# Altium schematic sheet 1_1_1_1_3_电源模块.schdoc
size 297 x 210 mm; Device: Sheet-Symbol; Symbol: Sheet-Symbol; Name: Sheet-Symbol; @Page No: 1; @Page Count: 2; @Schematic Name: 1_1_1_1_3_电源模块; @Project Name: Altium_Altium_Altium_新硬件设计比赛pcb1234567_2025-09-07_2025-09-08_2025-09-08; @Board Name: 1_1_1_1_3_电源模块; @Update Date: 2026-05-23; @Create Time: 14:33:01; @Update Time: 16:19:45; @Page Name: 1_1_1_1_3_电源模块; @Create Date: 2026-05-21
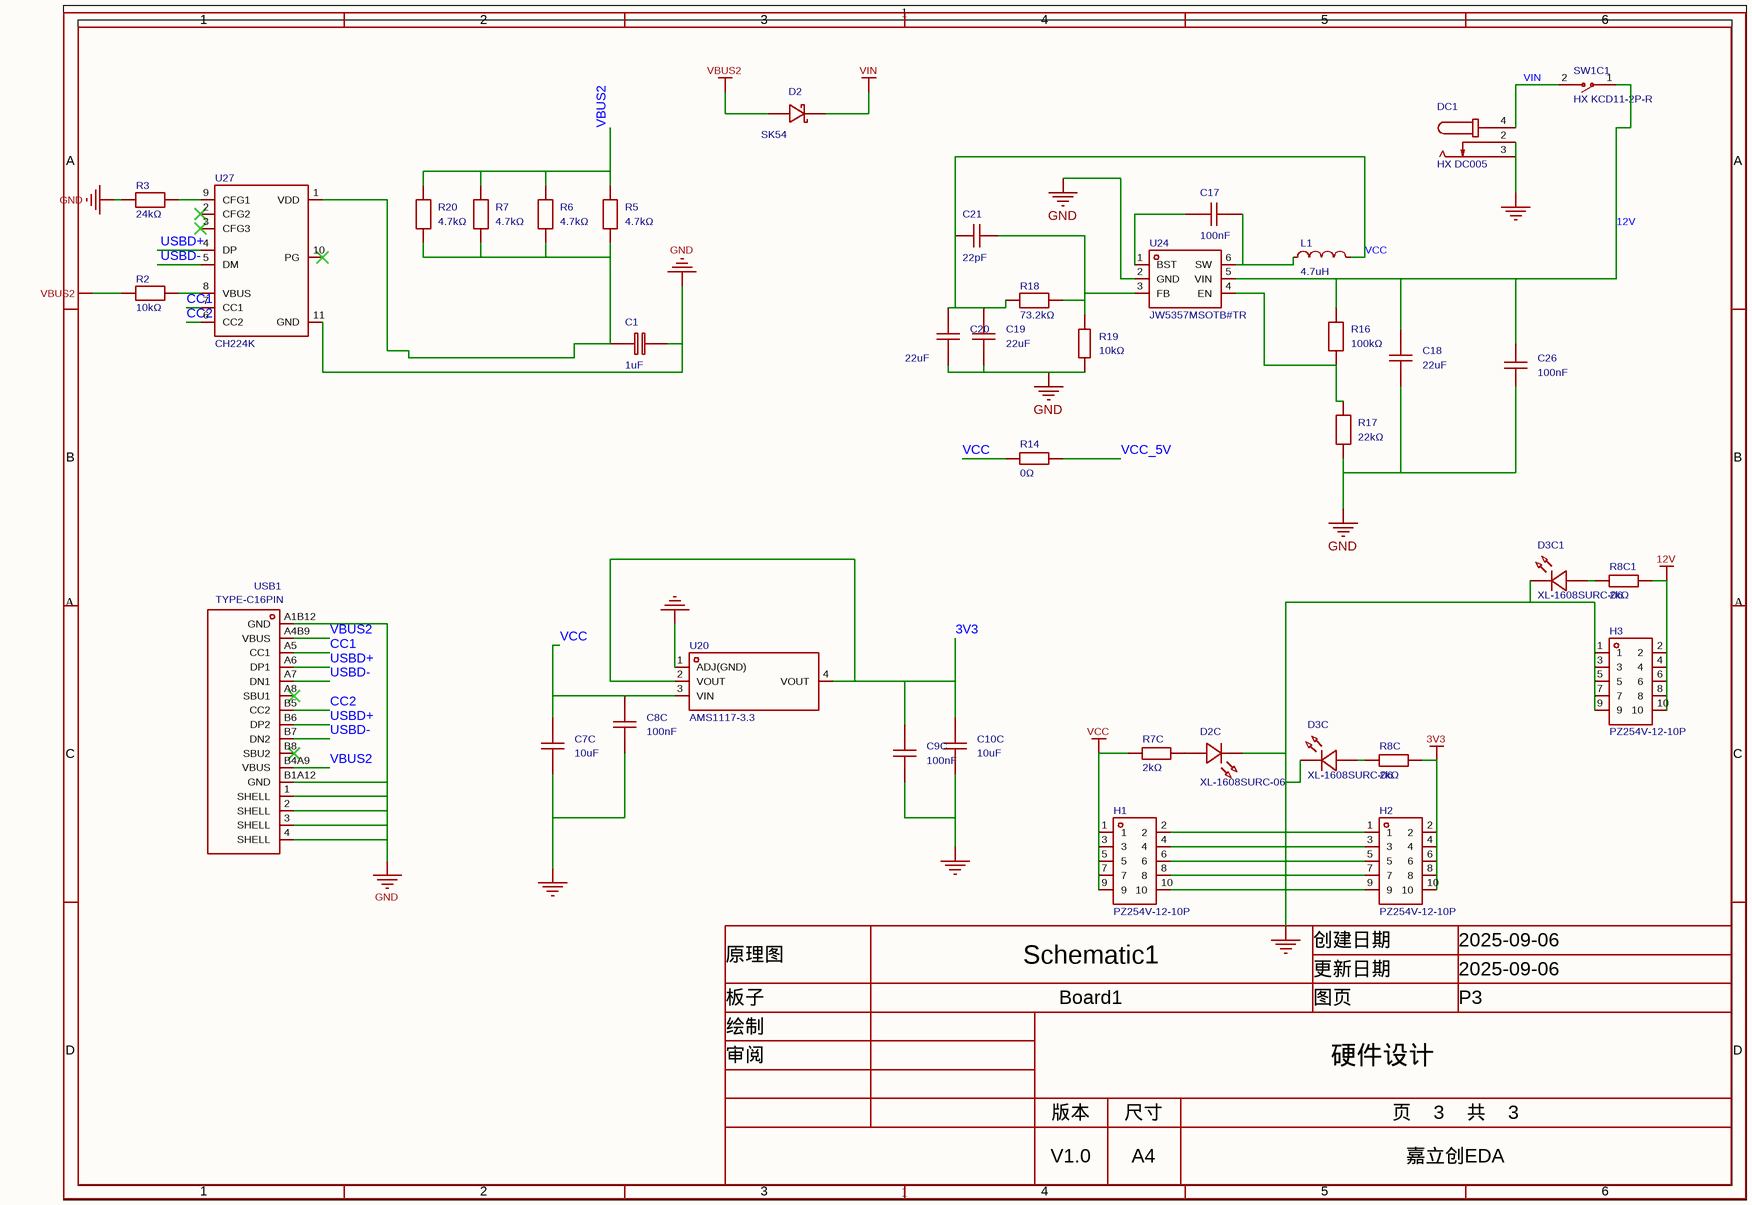
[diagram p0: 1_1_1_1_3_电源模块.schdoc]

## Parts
C1  1uF  [C0805]
C7C  10uF  [C0805]
C8C  100nF  [C0805]
C9C  100nF  [C0805]
C10C  10uF  [C0805]
C17  100nF  [C0603]
C18  22uF  [C0805]
C19  22uF  [C0805]
C20  22uF  [C0805]
C21  22pF  [C0603]
C26  100nF  [C0805]
D2  SK54  [SMB_L4.6-W3.6-LS5.3-RD]
D2C  XL-1608SURC-06  [LED0603-RD_RED]
D3C  XL-1608SURC-06  [LED0603-RD_RED]
D3C1  XL-1608SURC-06  [LED0603-RD_RED]
DC1  HX DC005  [DC-IN-TH_HANXIA_HX-DC005-QT]
H1  PZ254V-12-10P  [HDR-TH_10P-P2.54-V-M-R2-C5-S2.54]
H2  PZ254V-12-10P  [HDR-TH_10P-P2.54-V-M-R2-C5-S2.54]
H3  PZ254V-12-10P  [HDR-TH_10P-P2.54-V-M-R2-C5-S2.54]
L1  4.7uH  [IND-SMD_L7.0-W6.6]
R2  10kΩ  [R0603]
R3  24kΩ  [R0603]
R5  4.7kΩ  [R0805]
R6  4.7kΩ  [R0805]
R7  4.7kΩ  [R0805]
R7C  2kΩ  [R0603]
R8C  2kΩ  [R0603]
R8C1  2kΩ  [R0603]
R14  0Ω  [R0603]
R16  100kΩ  [R0603]
R17  22kΩ  [R0603]
R18  73.2kΩ  [R0603]
R19  10kΩ  [R0603]
R20  4.7kΩ  [R0805]
SW1C1  HX KCD11-2P-R  [SW-TH_2P-L15.0-W10.5-P5.00_KCD11-2P-R]
U20  AMS1117-3.3  [SOT-223-3_L6.5-W3.4-P2.30-LS7.0-BR]
U24  JW5357MSOTB#TR  [SOT-23-6_L2.9-W1.6-P0.95-LS2.8-BL]
U27  CH224K  [ESSOP-10_L4.9-W3.9-P1.0-LS6.0-TL-EP]
USB1  TYPE-C16PIN  [USB-C-SMD_TYPE-C16PIN]

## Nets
3V3: C9C.2 C10C.2 H2.2 H2.4 H2.6 H2.8 H2.10 R8C.2 U20.2(VOUT) U20.4(VOUT)
12V: C18.2 C26.2 H3.2 H3.4 H3.6 H3.8 H3.10 R8C1.2 R16.2 SW1C1.1 U24.5(VIN)
GND: C1.1 C7C.1 C8C.1 C9C.1 C10C.1 C18.1 C19.1 C20.1 C26.1 D2C.1(K) D3C.1(K) D3C1.1(K) DC1.2 DC1.3 H1.2 H1.4 H1.6 H1.8 H1.10 H2.1 H2.3 H2.5 H2.7 H2.9 H3.1 H3.3 H3.5 H3.7 H3.9 R3.2 R17.1 R19.1 U20.1(ADJ(GND)) U24.2(GND) U27.11(GND) USB1.1(SHELL) USB1.2(SHELL) USB1.3(SHELL) USB1.4(SHELL) USB1.A1B12(GND) USB1.B1A12(GND)
VBUS2: D2.2(A) R2.2 R5.1 R6.1 R7.1 R20.1 USB1.A4B9(VBUS) USB1.B4A9(VBUS)
VCC: C7C.2 C8C.2 C19.2 C20.2 C21.1 H1.1 H1.3 H1.5 H1.7 H1.9 L1.2 R7C.1 R14.1 R18.1 U20.3(VIN)
VIN: D2.1(C) DC1.4 SW1C1.2
CC1: U27.7(CC1) USB1.A5(CC1)
CC2: U27.6(CC2) USB1.B5(CC2)
USBD+: U27.4(DP) USB1.A6(DP1) USB1.B6(DP2)
USBD-: U27.5(DM) USB1.A7(DN1) USB1.B7(DN2)
VCC_5V: R14.2
NetC1_2: C1.2 R5.2 R6.2 R7.2 R20.2 U27.1(VDD)
NetC17_1: C17.1 U24.1(BST)
NetC17_2: C17.2 L1.1 U24.6(SW)
NetC21_2: C21.2 R18.2 R19.2 U24.3(FB)
NetD2C_2: D2C.2(A) R7C.2
NetD3C1_2: D3C1.2(A) R8C1.1
NetD3C_2: D3C.2(A) R8C.1
NetR2_1: R2.1 U27.8(VBUS)
NetR3_1: R3.1 U27.9(CFG1)
NetR16_1: R16.1 R17.2 U24.4(EN)

Not connected (* = marked no-connect by the designer): U27 2(CFG2)* 3(CFG3)* 10(PG)*; USB1 A8(SBU1)* B8(SBU2)*

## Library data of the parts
C1 = 0805B105K500NT: 容值:1uF;精度:±10%;额定电压:50V;温度系数:X7R;; Manufacturer: FH(风华); SymbolName: 0805B105K500NT_C215803; nameAlias: Value(F); Contributor: LCEDA_Lib; Convert to PCB: yes; Channel ID: $1e7147; 3D Model: 1ba041120af144c991958decab20d2410819f05c4eef4c71ace90d822a990e87; 3D Model Transform: 78.74,51.181,0,0,0,0,0,0.0005,0; Tolerance: ±10%; Voltage Rating: 50V; Temperature Coefficient: X7R; PCB Layer: TopLayer; ModelName: C0805_L2.0-W1.3-H1.3
C7C = GRM21BR61H106KE43L: 容值:10uF;精度:±10%;额定电压:50V;材质(温度系数):X5R;; Manufacturer: muRata(村田); Symbol: CAP_0805; Convert to PCB: yes; 3D Model: 1ba041120af144c991958decab20d241; 3D Model Transform: 78.74,51.181,0,0,0,0,0,0.0005,0; Tolerance: ±10%; Voltage Rated: 50V; Temperature Coefficient: X5R; ModelName: C0805_L2.0-W1.3-H1.3
C8C C9C = CC0805KRX7R9BB104: 容值:100nF;精度:±10%;额定电压:50V;温度系数:X7R;; Manufacturer: YAGEO(国巨); Symbol: CAP_0805; Convert to PCB: yes; ModelId: 1ba041120af144c991958decab20d241; ModelName: C0805_L2.0-W1.3-H1.3; ModelTransform: 78.74,51.181,0,0,0,0,0,0.0005,0; Tolerance: ±10%; Voltage Rating: 50V; Temperature Coefficient: X7R
C10C = GRM21BR61H106KE43L: 容值:10uF;精度:±10%;额定电压:50V;材质(温度系数):X5R;; Manufacturer: muRata(村田); Symbol: CAP_0805; Convert to PCB: yes; ModelId: 1ba041120af144c991958decab20d241; ModelName: C0805_L2.0-W1.3-H1.3; ModelTransform: 78.74,51.181,0,0,0,0,0,0.0005,0; Tolerance: ±10%; Voltage Rated: 50V; Temperature Coefficient: X5R
C17 = FCC0603B104K500CT: 容值:100nF;精度:±10%;额定电压:50V;温度系数:X7R;; Manufacturer: FOJAN(富捷); Channel ID: $1e5077; Add into BOM: yes; Tolerance: ±10%; Voltage Rating: 50V; Temperature Coefficient: X7R; PCB Layer: TopLayer; ModelId: ac125912035d415993ca9572d50418b10819f05c4eef4c71ace90d822a990e87; ModelName: C0603_L1.6-W0.8-H0.8; ModelTransform: 62.992,31.496,0,0,0,0,0,0,0
C18 = HGC0805R5226M350NSLJ: 容值:22uF;精度:±20%;额定电压:35V;温度系数:X5R;; Manufacturer: Chinocera(华瓷); Channel ID: $1e5236; Add into BOM: yes; Tolerance: ±20%; Voltage Rating: 35V; Temperature Coefficient: X5R; PCB Layer: TopLayer; ModelId: 1ba041120af144c991958decab20d2410819f05c4eef4c71ace90d822a990e87; ModelName: C0805_L2.0-W1.3-H1.3; ModelTransform: 78.74,51.181,0,0,0,0,0,0.0005,0
C19 = HGC0805R5226M350NSLJ: 容值:22uF;精度:±20%;额定电压:35V;温度系数:X5R;; Manufacturer: Chinocera(华瓷); Channel ID: $1e5382; Add into BOM: yes; Tolerance: ±20%; Voltage Rating: 35V; Temperature Coefficient: X5R; PCB Layer: TopLayer; ModelId: 1ba041120af144c991958decab20d2410819f05c4eef4c71ace90d822a990e87; ModelName: C0805_L2.0-W1.3-H1.3; ModelTransform: 78.74,51.181,0,0,0,0,0,0.0005,0
C20 = HGC0805R5226M350NSLJ: 容值:22uF;精度:±20%;额定电压:35V;温度系数:X5R;; Manufacturer: Chinocera(华瓷); Channel ID: $1e5412; Add into BOM: yes; Tolerance: ±20%; Voltage Rating: 35V; Temperature Coefficient: X5R; PCB Layer: TopLayer; ModelId: 1ba041120af144c991958decab20d2410819f05c4eef4c71ace90d822a990e87; ModelName: C0805_L2.0-W1.3-H1.3; ModelTransform: 78.74,51.181,0,0,0,0,0,0.0005,0
C21 = CC0603JRNPO9BN220: 容值:22pF;精度:±5%;额定电压:50V;温度系数:NP0;; Manufacturer: YAGEO(国巨); Channel ID: $1e5442; Add into BOM: yes; Tolerance: ±5%; Voltage Rating: 50V; Temperature Coefficient: NP0; PCB Layer: TopLayer; ModelId: ac125912035d415993ca9572d50418b10819f05c4eef4c71ace90d822a990e87; ModelName: C0603_L1.6-W0.8-H0.8; ModelTransform: 62.992,31.496,0,0,0,0,0,0,0
C26 = 0805B104K500NT: 容值:100nF;精度:±10%;额定电压:50V;温度系数:X7R;; Manufacturer: FH(风华); Channel ID: $1e10077; Add into BOM: yes; Tolerance: ±10%; Voltage Rating: 50V; Temperature Coefficient: X7R; PCB Layer: TopLayer; ModelId: 1ba041120af144c991958decab20d2410819f05c4eef4c71ace90d822a990e87; ModelName: C0805_L2.0-W1.3-H1.3; ModelTransform: 78.74,51.181,0,0,0,0,0,0.0005,0
D2 = SK54_C84171: 正向压降(Vf):550mV@5A;直流反向耐压(Vr):40V;整流电流:5A;; Manufacturer: DIYI(迪一/芯诺); Convert to PCB: yes; ModelId: 5e8926c661484ff2a35b83e5ae62aeb9; ModelTransform: 212.598,141.732,0,0,0,0,0,0,0; Voltage - DC Reverse(Vr): 40V; Current - Rectified: 5A; Reverse Leakage Current (Ir): 100uA@40V; Operating Junction Temperature Range: -55℃~+150℃; Non-Repetitive Peak Forward Surge Current: 100A
D2C = XL-1608SURC-06: Manufacturer: XINGLIGHT(成兴光); Add into BOM: yes; Illumination Color: 红色; Voltage - Forward(Vf): 2.3V; Power(Watts): 50mW; Forward Current: 20mA; Wavelength - Dominant: 620nm~630nm; Peak Wavelength: 625nm; Lens Color: 无色透明透镜; Luminous Intensity: 225mcd; Viewing Angle: 120°; 3D Model: 74041d3a270d435c8600a9ab9b7641c0; Channel ID: $1ie575; PCB Layer: TopLayer
D3C = XL-1608SURC-06: Manufacturer: XINGLIGHT(成兴光); Add into BOM: yes; Illumination Color: 红色; Voltage - Forward(Vf): 2.3V; Power(Watts): 50mW; Forward Current: 20mA; Wavelength - Dominant: 620nm~630nm; Peak Wavelength: 625nm; Lens Color: 无色透明透镜; Luminous Intensity: 225mcd; Viewing Angle: 120°; 3D Model: 74041d3a270d435c8600a9ab9b7641c0; Channel ID: $1ie611; PCB Layer: TopLayer
D3C1 = XL-1608SURC-06: Manufacturer: XINGLIGHT(成兴光); Add into BOM: yes; Illumination Color: 红色; Voltage - Forward(Vf): 2.3V; Power(Watts): 50mW; Forward Current: 20mA; Wavelength - Dominant: 620nm~630nm; Peak Wavelength: 625nm; Lens Color: 无色透明透镜; Luminous Intensity: 225mcd; Viewing Angle: 120°; 3D Model: 74041d3a270d435c8600a9ab9b7641c0; Channel ID: $1e10207; PCB Layer: TopLayer
DC1 = HX DC005: 连接器类型:DC电源插座;安装方式:弯插;触点内径:2mm;触点外径:6.3mm;额定电流:1A;额定电压:30V;工作温度:-25℃~+70℃;; Manufacturer: hanxia(韩下); Add into BOM: yes; Connector Type: DC电源插座; Inside Contact Diameter: 2mm; Outside Contact Diameter: 6.3mm; Voltage Rating (Max): 30V; 3D Model: 60961acdddac43b885ceb5916a70ead0; 3D Model Transform: 559.054,364.173,0,0,0,0,-139.767,86.612,-161.417; Current Rating: 1A
H1-H3 = PZ254V-12-10P: Manufacturer: XFCN(兴飞); Add into BOM: yes; Pin Structure: 2x5P; Pitch: 2.54mm; Circluar Pins/Square Pins: 方针; ModelId: c4cfba895466416fb2f10be924625d31
L1 = FXL0630-4R7-M: 电感值:4.7uH;精度:±20%;额定电流:6A;饱和电流(Isat):9A;类型:一体成型电感;; Manufacturer: cjiang(长江微电); AddInBom: yes; ModelId: 6860c29aec394a38a0f014af7f722a42; ModelName: IND-SMD_L7.0-W6.6-H3.0; ModelTransform: 275.59,259.88137,0,0,0,0,0,0,0; Tolerance: ±20%; Current Rating: 6A; Current - Saturation(Isat): 9A; DC Resistance(DCR): 33mΩ; Type: 一体成型电感
R2 = RCA0310KJLF: 电阻类型:厚膜电阻;阻值:10kΩ;精度:±5%;功率:100mW;工作电压:75V;温度系数:±100ppm/℃;; Manufacturer: HKR(香港电阻); nameAlias: Value(Ω); Contributor: LCEDA_Lib; Convert to PCB: yes; Channel ID: $1e7062; 3D Model Transform: 31.8897,63.7794,0,90,0,0,0,0,0; Tolerance: ±5%; Power(Watts): 100mW; Voltage-Supply(Max): 75V; PCB Layer: TopLayer; ModelId: fc143cca1e79419f9cd78b61e9279f080819f05c4eef4c71ace90d822a990e87
R3 = FRC0603F2402TS: 电阻类型:厚膜电阻;阻值:24kΩ;精度:±1%;功率:100mW;工作电压:75V;温度系数:±100ppm/℃;; Manufacturer: FOJAN(富捷); Add into BOM: yes; 3D Model: fc143cca1e79419f9cd78b61e9279f08; 3D Model Transform: 31.8897,63.7794,0,90,0,0,0,0,0; Tolerance: ±1%; Power(Watts): 100mW; Voltage-Supply(Max): 75V
R5 = FRC0805F4701TS: 电阻类型:厚膜电阻;阻值:4.7kΩ;精度:±1%;功率:125mW;工作电压:150V;温度系数:±100ppm/℃;; Manufacturer: FOJAN(富捷); nameAlias: Value(Ω); Contributor: LCEDA_Lib; Convert to PCB: yes; Channel ID: $1e7118; 3D Model Transform: 78.74,51.181,0,0,0,0,0,-0.0005,0; Tolerance: ±1%; Power(Watts): 125mW; Voltage-Supply(Max): 150V; PCB Layer: TopLayer; ModelId: 37a81e68749a4138bd2dfa6897b24b850819f05c4eef4c71ace90d822a990e87; ModelName: R0805_L2.0-W1.3-H0.6
R6 = FRC0805F4701TS: 电阻类型:厚膜电阻;阻值:4.7kΩ;精度:±1%;功率:125mW;工作电压:150V;温度系数:±100ppm/℃;; Manufacturer: FOJAN(富捷); nameAlias: Value(Ω); Contributor: LCEDA_Lib; Convert to PCB: yes; Channel ID: $1e7174; 3D Model Transform: 78.74,51.181,0,0,0,0,0,-0.0005,0; Tolerance: ±1%; Power(Watts): 125mW; Voltage-Supply(Max): 150V; PCB Layer: TopLayer; ModelId: 37a81e68749a4138bd2dfa6897b24b850819f05c4eef4c71ace90d822a990e87; ModelName: R0805_L2.0-W1.3-H0.6
R7 = FRC0805F4701TS: 电阻类型:厚膜电阻;阻值:4.7kΩ;精度:±1%;功率:125mW;工作电压:150V;温度系数:±100ppm/℃;; Manufacturer: FOJAN(富捷); nameAlias: Value(Ω); Contributor: LCEDA_Lib; Convert to PCB: yes; Channel ID: $1e7203; 3D Model Transform: 78.74,51.181,0,0,0,0,0,-0.0005,0; Tolerance: ±1%; Power(Watts): 125mW; Voltage-Supply(Max): 150V; PCB Layer: TopLayer; ModelId: 37a81e68749a4138bd2dfa6897b24b850819f05c4eef4c71ace90d822a990e87; ModelName: R0805_L2.0-W1.3-H0.6
R7C R8C R8C1 = 0603WAF2001T5E: 电阻类型:厚膜电阻;阻值:2kΩ;精度:±1%;功率:100mW;工作电压:75V;温度系数:±100ppm/℃;; Manufacturer: UNI-ROYAL(厚声); Symbol: Res_0603; Convert to PCB: yes; ModelId: fc143cca1e79419f9cd78b61e9279f08; ModelTransform: 31.8897,63.7794,0,90,0,0,0,0,0; Tolerance: ±1%; Power(Watts): 100mW; Voltage-Supply(Max): 75V
R14 = 0603WAF0000T5E: 电阻类型:厚膜电阻;阻值:0Ω;精度:±1%;功率:100mW;工作电压:75V;温度系数:-;; Manufacturer: UNI-ROYAL(厚声); Symbol: Res_0603; Convert to PCB: yes; ModelId: fc143cca1e79419f9cd78b61e9279f08; ModelTransform: 31.8897,63.7794,0,90,0,0,0,0,0; Tolerance: ±1%; Power(Watts): 100mW; Voltage-Supply(Max): 75V
R16 = RCA03100KFLF: 电阻类型:厚膜电阻;阻值:100kΩ;精度:±1%;功率:100mW;工作电压:75V;温度系数:±100ppm/℃;; Manufacturer: HKR(香港电阻); Channel ID: $1e5123; Add into BOM: yes; Tolerance: ±1%; Power(Watts): 100mW; Voltage-Supply(Max): 75V; PCB Layer: TopLayer; ModelId: fc143cca1e79419f9cd78b61e9279f080819f05c4eef4c71ace90d822a990e87; ModelTransform: 31.8897,63.7794,0,90,0,0,0,0,0
R17 = FRC0603F2202TS: 电阻类型:厚膜电阻;阻值:22kΩ;精度:±1%;功率:100mW;工作电压:75V;温度系数:±100ppm/℃;; Manufacturer: FOJAN(富捷); Channel ID: $1e5153; Add into BOM: yes; Tolerance: ±1%; Power(Watts): 100mW; Voltage-Supply(Max): 75V; PCB Layer: TopLayer; ModelId: fc143cca1e79419f9cd78b61e9279f080819f05c4eef4c71ace90d822a990e87; ModelTransform: 31.8897,63.7794,0,90,0,0,0,0,0
R18 = FRC0603F7322TS: 电阻类型:厚膜电阻;阻值:73.2kΩ;精度:±1%;功率:100mW;工作电压:75V;温度系数:±100ppm/℃;; Manufacturer: FOJAN(富捷); Channel ID: $1e5322; Add into BOM: yes; Tolerance: ±1%; Power(Watts): 100mW; Voltage-Supply(Max): 75V; PCB Layer: TopLayer; ModelId: fc143cca1e79419f9cd78b61e9279f080819f05c4eef4c71ace90d822a990e87; ModelTransform: 31.8897,63.7794,0,90,0,0,0,0,0
R19 = ARG03FTC1002: 电阻类型:薄膜电阻;阻值:10kΩ;精度:±1%;功率:100mW;工作电压:75V;温度系数:±25ppm/℃;; Manufacturer: Viking(光颉); Add into BOM: yes; 3D Model: fc143cca1e79419f9cd78b61e9279f08; 3D Model Transform: 31.8897,63.7794,0,90,0,0,0,0,0; Tolerance: ±1%; Power(Watts): 100mW; Voltage-Supply(Max): 75V
R20 = FRC0805F4701TS: 电阻类型:厚膜电阻;阻值:4.7kΩ;精度:±1%;功率:125mW;工作电压:150V;温度系数:±100ppm/℃;; Manufacturer: FOJAN(富捷); nameAlias: Value(Ω); Contributor: LCEDA_Lib; Convert to PCB: yes; Channel ID: $1e7232; 3D Model Transform: 78.74,51.181,0,0,0,0,0,-0.0005,0; Tolerance: ±1%; Power(Watts): 125mW; Voltage-Supply(Max): 150V; PCB Layer: TopLayer; ModelId: 37a81e68749a4138bd2dfa6897b24b850819f05c4eef4c71ace90d822a990e87; ModelName: R0805_L2.0-W1.3-H0.6
SW1C1 = HX KCD11-2P-R: 带灯:无;引脚样式:焊片;额定电流:3A;额定电压(AC):250V;电路结构:单刀单掷;工作寿命:1万次;; Manufacturer: hanxia(韩下); Add into BOM: yes; With Lamp: 无; Actuator Color: 红色; Voltage Rating (AC): 250V; Circuit: 单刀单掷; 3D Model: b6a28d0ffc1348d1acceb24f6a991b59; 3D Model Transform: 590.55,413.385,0,0,0,0,100.394,0,-196.85; Current Rating: 3A; Life: 1万次
U20 = AMS1117-3.3: Manufacturer: YONGYUTAI(永裕泰); Add into BOM: yes; Output Type: 固定; Voltage - Supply: 18V; Output Voltage: 3.3V; Output Current: 1A; Power Supply Rejection Ratio (PSRR): 60dB@(120Hz); Voltage Dropout: 1.3V@(1A); standby current: 10mA; Noise: 0.005%Vout; Output Configuration: 正极; Number of Outputs: 1
U24 = JW5357MSOTB#TR: 功能类型:降压型;工作电压:4.5V~18V;输出电流:3A;输出类型:可调;; Manufacturer: Joulwatt(杰华特); AddInBom: yes; ModelId: 18da8f6c14a34920b3e136b5c401a119; ModelName: SOT-23-6_L2.9-W1.6-H1.5-LS2.8-P0.95; ModelTransform: 110.236,113.364,0,90,0,0,0.0005,0.0005,0; Function: 降压型; Output Current: 3A; Frequency - Switching: 600kHz; Topology: 降压式; Quiescent Current: 220uA; Switch tube (built-in/external): 内置; Output Type: 可调
U27 = CH224K: CH224Q/CH224A 为支持USB PD3.2 的USB PD 快充协议受电芯片，最高支持PD3.2 EPR 140W 功率，并支持单电阻配置、I/O 电平配置及I2C 配置。通过I2C 接口可以读取协议握手状态和读取当前PD 档位额定电流。芯片内置高压LDO，静态功耗低，集成度高，外围精简。芯片集成输出电压检测及过压保护功能，可广泛应用于各类电子设备拓展高功率输入如无线充电器、小家电、锂电池电动工具等各类场合。; Manufacturer: WCH(南京沁恒); AddInBom: yes; ModelId: fa9ab07a8bf349a28ad4bf9fc4af4163; ModelTransform: 192.913,236.22,0,0,0,0,0,0,0; Output Power: 100W; Output Voltage: 5V；20V；15V；12V；9V
USB1 = TYPE-C16PIN: 连接器类型:Type-C;协议标准:-;公母:母;安装方式:卧贴;触点数量:16P;端口数量:1;额定电流 - 电源:3A;工作温度:-40℃~+85℃;; Manufacturer: SHOU HAN(首韩); Contributor: LCSC; Convert to PCB: yes; ModelId: d6783d3a2268456b863f42d3286191d0; ModelTransform: 351.9678,311.023,0,180,0,0,0,-41.85,-39.37; Connector Type: Type-C; Gender: 母; Number of Contacts: 16P; Number of Ports: 1; Current Rating-Power: 3A; Voltage Rating: 30V; Connect-Disconnect Life: 1万次; Detection color: 黑色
